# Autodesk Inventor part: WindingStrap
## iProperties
Author: Administrator
Shininess: 20.0
PropertySet Name: _Private Model Information
Created: 2001-04
Part Number: WindingStrap
Document SubType Name: Modeling
Designer: Administrator
Control State: 0
Master: False
Checked Out: False
PropertySet Name: Design Tracking Control
Density: 0.0
Volumn: 0.0
Area: 0.0
PropertySet Name: Model Information
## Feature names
1. Extrusion1
